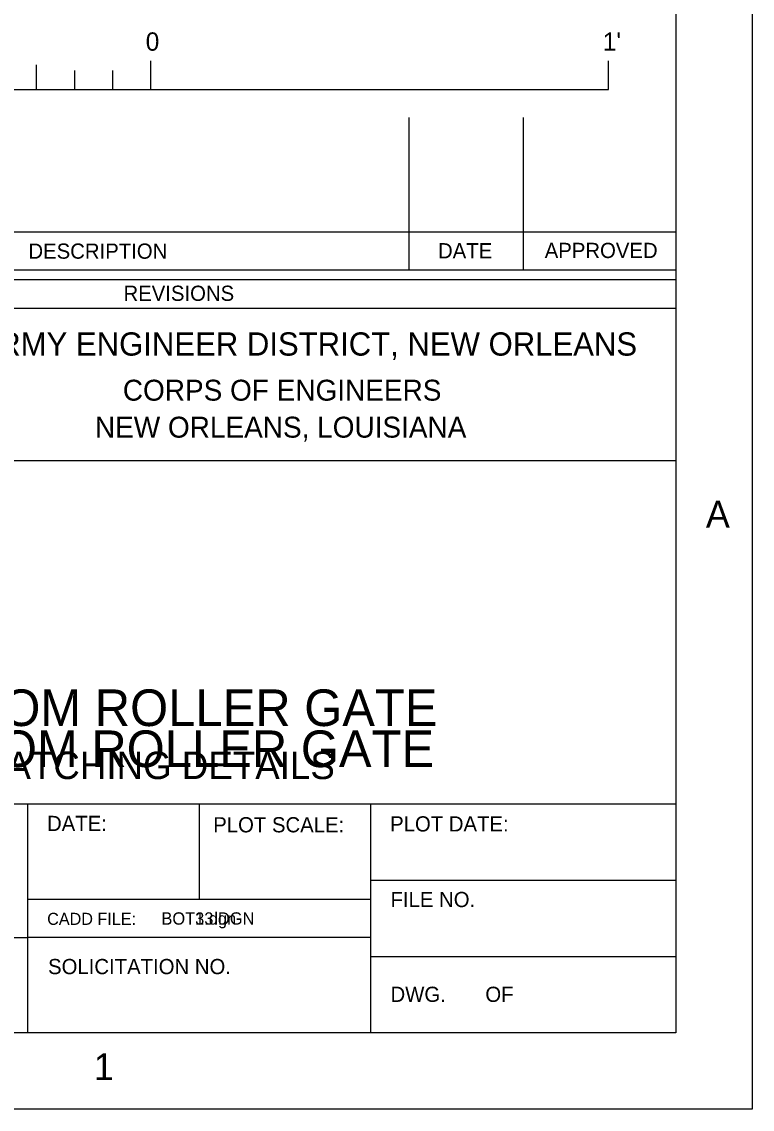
# Model space of a CAD drawing. Extents: x 0 to 53.3, y -2.9 to 37.3.
# Drawn here: x 46.94 to 53.33, y 0 to 9.51 of the extents above; entities that cross this region are included whole.
import ezdxf

# ---------------------------------------------------------------- set-up
doc = ezdxf.new("R2010")
doc.units = 0
doc.layers.add('Level 1', color=7, linetype='Continuous')
doc.layers.add('Level 2', color=7, linetype='Continuous')

msp = doc.modelspace()

# ---------------------------------------------------------------- linework, layer by layer
at = {"layer": 'Level 1'}
for p, q in [((47.0743, 8.9139), (47.0743, 9.1284)), ((48.0743, 8.9139), (48.0743, 9.1639)), ((52.0743, 8.9139), (52.0743, 9.1639)), ((47.4076, 8.9139), (47.4076, 9.0805)), ((47.741, 8.9139), (47.741, 9.0805)), ((44.0743, 8.9139), (52.0743, 8.9139)), ((50.3308, 7.3348), (50.3308, 8.6682)), ((51.3308, 7.3348), (51.3308, 8.6682)), ((52.6641, 7.6682), (43.9974, 7.6682)), ((52.6641, 7.3348), (43.9974, 7.3348)), ((52.6641, 7.2515), (43.9974, 7.2515)), ((52.6641, 7.0015), (43.9974, 7.0015)), ((52.6641, 5.6682), (43.9974, 5.6682)), ((52.6641, 2.6682), (43.9974, 2.6682)), ((46.9974, 0.6682), (46.9974, 2.6682)), ((48.4974, 1.8348), (48.4974, 2.6682)), ((49.9974, 0.6682), (49.9974, 2.6682)), ((52.6641, 2.0015), (49.9974, 2.0015)), ((49.9974, 1.8348), (46.9974, 1.8348)), ((43.9974, 1.5015), (46.9974, 1.5015)), ((49.9974, 1.5015), (46.9974, 1.5015)), ((52.6641, 1.3348), (49.9974, 1.3348))]:
    msp.add_line(p, q, dxfattribs=at)
for points in [[(-0.0026, 37.3348), (53.3308, 37.3348), (53.3308, 0.0015), (-0.0026, 0.0015)], [(1.9974, 36.6682), (52.6641, 36.6682), (52.6641, 0.6682), (1.9974, 0.6682)]]:
    msp.add_lwpolyline(points, close=True, dxfattribs=at)

# ---------------------------------------------------------------- texts
for s, height, p in [('0', 0.16, (48.0281, 9.2534)), ("1'", 0.16, (52.024, 9.2534)), ('DESCRIPTION', 0.132833, (47.0028, 7.4353)), ('DATE', 0.13283, (50.5834, 7.4385)), ('APPROVED', 0.13283, (51.5164, 7.4413)), ('REVISIONS', 0.13283, (47.8339, 7.0668)), ('U.S. ARMY ENGINEER DISTRICT, NEW ORLEANS', 0.203167, (45.9539, 6.5885)), ('CORPS OF ENGINEERS', 0.18285, (47.8281, 6.1947)), ('NEW ORLEANS, LOUISIANA', 0.18285, (47.5841, 5.8715)), ('A', 0.2337, (52.9258, 5.086)), ('DATE:', 0.13283, (47.1653, 2.4332)), ('PLOT SCALE:', 0.132833, (48.6183, 2.4215)), ('PLOT DATE:', 0.13283, (50.1648, 2.4292)), ('FILE NO.', 0.13283, (50.1684, 1.7683)), ('CADD FILE:', 0.10567, (47.1666, 1.6128)), ('SOLICITATION NO.', 0.132833, (47.1744, 1.1823)), ('DWG.       OF', 0.132833, (50.1684, 0.9397)), ('1', 0.2337, (47.5741, 0.2563))]:
    msp.add_text(s, height=height, dxfattribs=at).set_placement(p)
at = {"layer": 'Level 2'}
for s, height, p in [('BOTTOM ROLLER GATE', 0.32, (45.6334, 3.3508)), ('BOTTOM ROLLER GATE', 0.320063, (45.6032, 2.9921)), ('LATCHING DETAILS', 0.239997, (46.6319, 2.8872)), ('BOT3.dgn', 0.10718, (48.1658, 1.6148)), ('BOT13.DGN', 0.10717, (48.1658, 1.6155))]:
    msp.add_text(s, height=height, dxfattribs=at).set_placement(p)

doc.saveas('drawing.dxf')
